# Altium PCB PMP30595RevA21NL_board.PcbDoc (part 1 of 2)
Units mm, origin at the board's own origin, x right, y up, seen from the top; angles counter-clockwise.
Board outline 110.49 x 76.2 mm, 2 copper layers (Top Layer, Bottom Layer), stack 1.575 mm thick; 77 components, 38 nets, 187 pads, 95 vias.
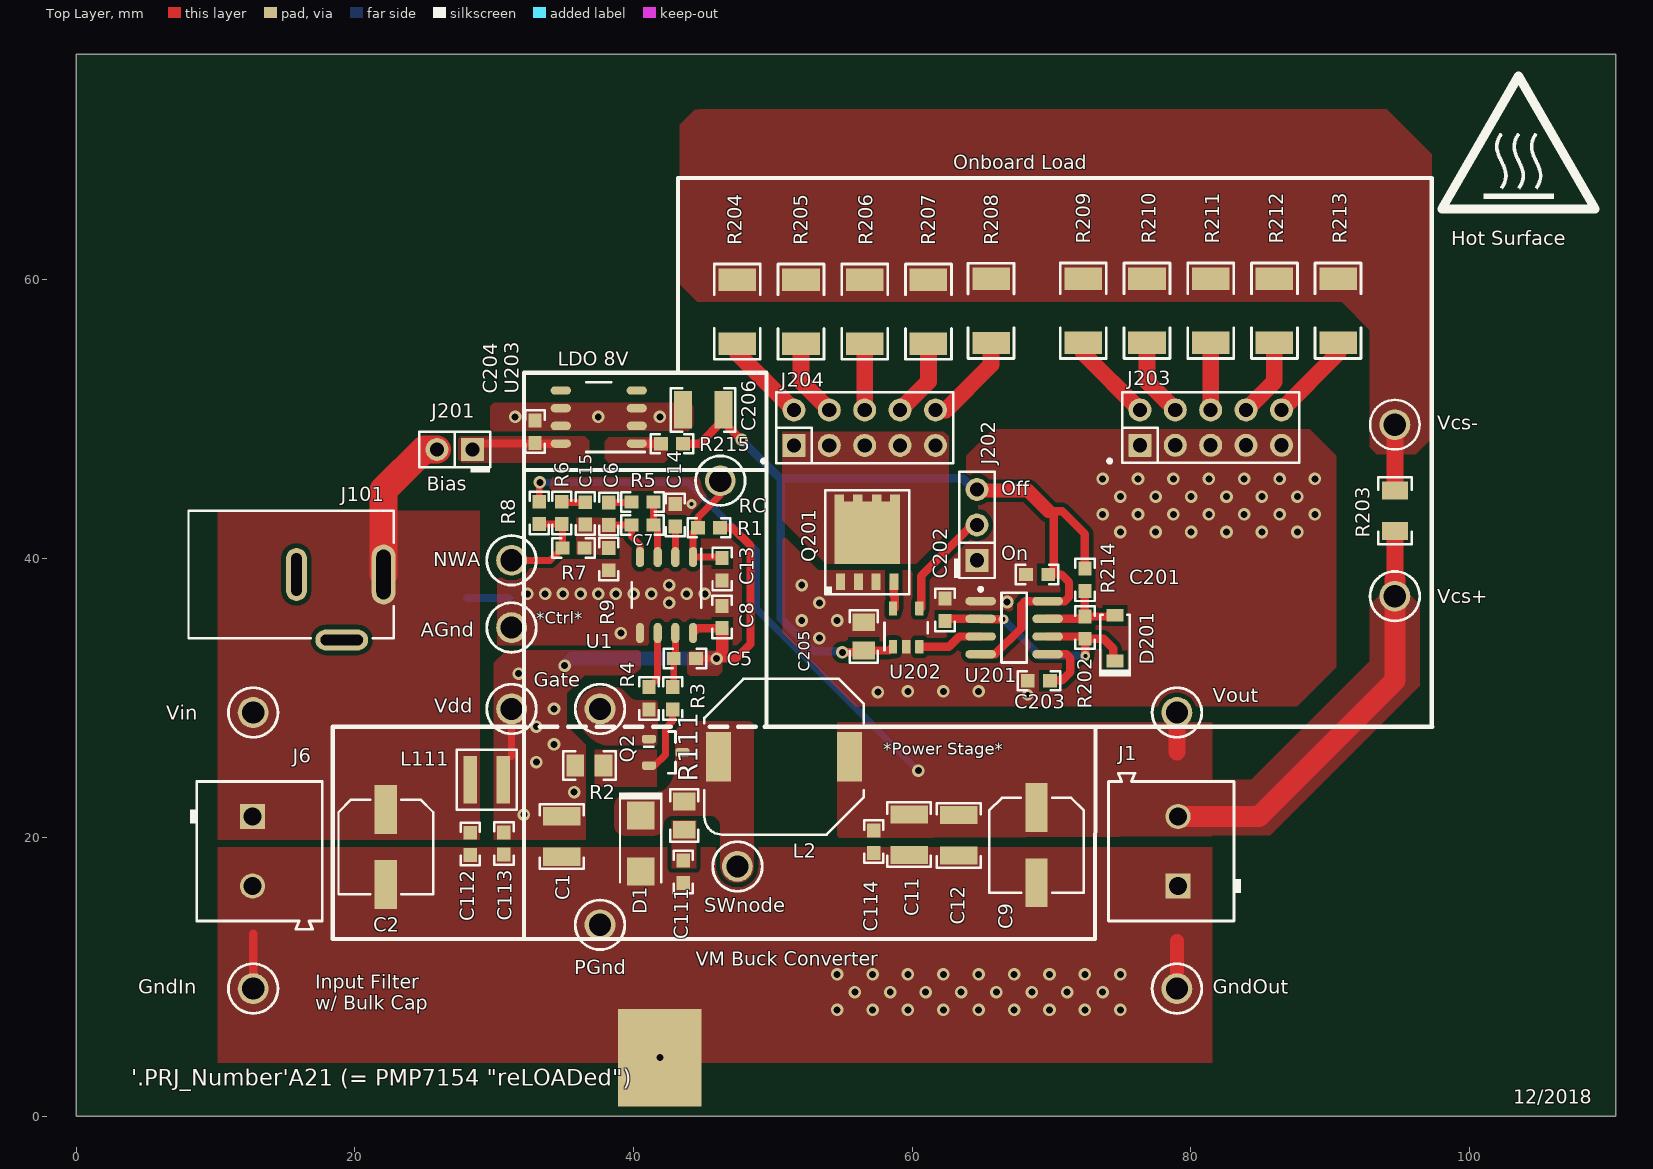
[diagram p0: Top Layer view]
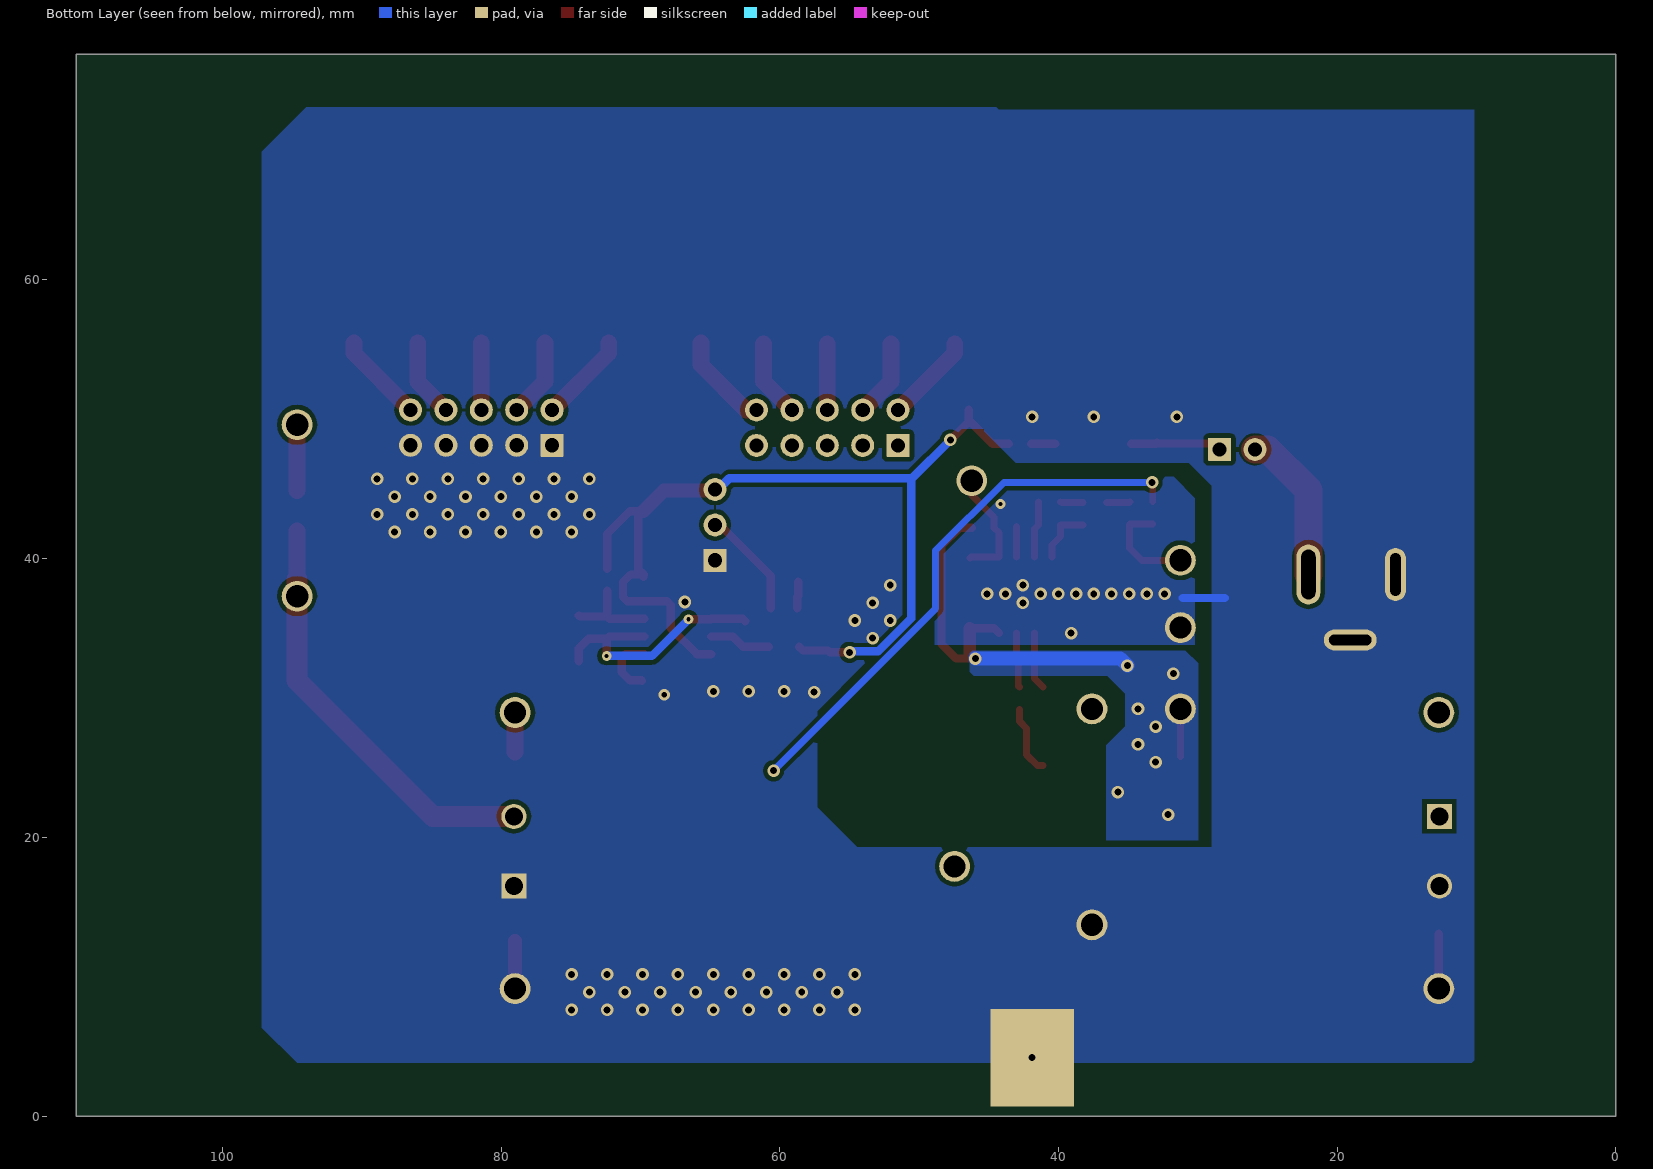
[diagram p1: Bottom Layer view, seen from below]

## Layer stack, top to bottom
Top Solder: solder mask 0.0102, Solder Resist, Dk 3.5
Top Layer: signal copper 0.0356
Dielectric1: core 1.5037, FR-4, Dk 4.8
Bottom Layer: signal copper 0.0356
Bottom Solder: solder mask 0.0102, Solder Resist, Dk 3.5

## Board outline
0,0 0,76.2 110.49,76.2 110.49,0

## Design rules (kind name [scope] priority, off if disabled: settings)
AcuteAngle [All] p1: minimum=4.50000000000000E+0001 checktracksonly=FALSE
AssemblyTestPointUsage [All] p1: valid=2
BoardOutlineClearance BoardOutlineClearance_MountingHoles [OnCopper and InComponentClass('Mounting Holes')] p1: gap=1 ignorepadtopadclearanceinfootprint=FALSE
BoardOutlineClearance BoardOutlineClearance_Poly [OnCopper and IsPoly] p2: gap=0.635 ignorepadtopadclearanceinfootprint=FALSE
BoardOutlineClearance [OnCopper and Not InComponentClass('Logo') and not InComponentClass('FiducialMark') and not InRegion(1000,500,4000,800) and not InPoly] p3: gap=1.905 ignorepadtopadclearanceinfootprint=FALSE
Clearance Clearance_Keepouts [((IsTrack Or IsArc) And Not InPoly) And IsFree and IsKeepOut vs ((IsTrack Or IsArc) And Not InPoly) And IsFree and IsKeepOut] p1: gap=0 ignorepadtopadclearanceinfootprint=FALSE
Clearance Clearance_Poly [InPolygon] p2: gap=0.32 ignorepadtopadclearanceinfootprint=TRUE
Clearance Clearance_FiducialMark [IsKeepOut and InComponentClass('FiducialMark') vs IsPad and InComponentClass('FiducialMark')] p3: gap=0 ignorepadtopadclearanceinfootprint=FALSE
Clearance [All] p4: gap=0.2 ignorepadtopadclearanceinfootprint=TRUE
ComponentClearance ComponentClearance_MountingHoles_FiducialMarks [InComponentClass('Mounting Holes') vs InComponentClass('FiducialMark')] p1: gap=1.27 collisioncheckmode=3 verticalgap=0.254 showdistances=FALSE
ComponentClearance ComponentClearance_Shunt [InComponentClass('Header') vs InComponentClass('Shunt')] p2: gap=0 collisioncheckmode=3 verticalgap=0 showdistances=FALSE
ComponentClearance ComponentClearance_Logo [InComponentClass('Logo')] p3: gap=1.27 collisioncheckmode=3 verticalgap=0.254 showdistances=FALSE
ComponentClearance ComponentClearance_ScrewToNut [(HasFootprint('NY PMS 440 0025 PH')) vs (HasFootprint('Keystone_1902C'))] p4: gap=0.127 collisioncheckmode=3 verticalgap=0.254 showdistances=FALSE
ComponentClearance ComponentClearance_MountingHoles [InComponentClass('Mounting Holes')] p5: gap=6.35 collisioncheckmode=3 verticalgap=2540 showdistances=FALSE
ComponentClearance ComponentClearance_SmallPassives [HasFootprint('0201*') or HasFootprint('0402*') or HasFootprint('0508') or HasFootprint('0603*') or HasFootprint('0612') or HasFootprint('0805*') or HasFootprint('0815*') or HasFootprint('0830*') or HasFootprint('1206*') or HasFootprint('1210*') or HasFootprint('1808*') or HasFootprint('1812*') or HasFootprint('1825*') or HasFootprint('2010*') or HasFootprint('2220*') or HasFootprint('2225*') or HasFootprint('2512*') or HasFootprint('2728*') or HasFootprint('3518*') vs HasFootprint('0201*') or HasFootprint('0402*') or HasFootprint('0508') or HasFootprint('0603*') or HasFootprint('0612') or HasFootprint('0805*') or HasFootprint('0815*') or HasFootprint('0830*') or HasFootprint('1206*') or HasFootprint('1210*') or HasFootprint('1808*') or HasFootprint('1812*') or HasFootprint('1825*') or HasFootprint('2010*') or HasFootprint('2220*') or HasFootprint('2225*') or HasFootprint('2512*') or HasFootprint('2728*') or HasFootprint('3518*')] p6: gap=0.38 collisioncheckmode=3 verticalgap=0.254 showdistances=FALSE
ComponentClearance ComponentClearance_THtoSMT [IsThruComponent vs IsSMTComponent] p7: gap=1.016 collisioncheckmode=3 verticalgap=0.762 showdistances=FALSE
ComponentClearance ComponentClearance_THtoTH [IsThruComponent vs IsThruComponent] p8: gap=0.762 collisioncheckmode=3 verticalgap=0.762 showdistances=FALSE
ComponentClearance [All] p9: gap=0.762 collisioncheckmode=3 verticalgap=0.254 showdistances=FALSE
DiffPairsRouting [All] p1: maxlimit=2.54 minlimit=0.254 mostfreqgap=0.254 toplayer_minwidth=0.381 toplayer_maxwidth=0.381 toplayer_prefwidth=0.381 bottomlayer_minwidth=0.381 bottomlayer_maxwidth=0.381 bottomlayer_prefwidth=0.381 maxuncoupledlength=25.4
FabricationTestPointUsage TestPointUsage [All] p1: valid=2 allowmultiple=FALSE
FabricationTestpoint Testpoint [All] p1: side=3 testpointundercomponent=TRUE minsize=1.016 maxsize=2.54 preferedsize=1.524 minholesize=0 maxholesize=1.016 preferedholesize=0.813 testpointgrid=0.025 allowsidetop=TRUE allowsidebottom=TRUE usegrid=TRUE gridtolerance=0
FanoutControl Fanout_LCC [IsLCC] p1: bgadir=Out bgaviamode=Centered fanoutstyle=Auto fanoutdirection=Alternating viagrid=0.025 // Fanout_LCC (Default Rule)
FanoutControl Fanout_BGA [IsBGA] p2: bgadir=Out bgaviamode=Centered fanoutstyle=Auto fanoutdirection=Alternating viagrid=0.025 // Fanout_BGA (Default Rule)
FanoutControl Fanout_Default [All] p4: bgadir=Out bgaviamode=Centered fanoutstyle=Auto fanoutdirection=Alternating viagrid=0.025 // Fanout_Default (Default Rule)
FanoutControl Fanout_Small [(CompPinCount < 5)] p5: bgadir=Out bgaviamode=Centered fanoutstyle=Auto fanoutdirection=OutThenIn viagrid=0.025 // Fanout_Small (Default Rule)
HoleSize [All] p1: absolutevalues=TRUE maxlimit=6.375 minlimit=0.3 maxpercent=80.000 minpercent=20.000
MinimumAnnularRing MinimumAnnularRing_ThermalPadVias [IsVia and InAnyComponent] p1: minimumring=0.15
MinimumAnnularRing [All] p2: minimumring=0.2
MinimumSolderMaskSliver MinimumSolderMaskSliver_Logo [InComponentClass('Logo') vs InComponentClass('Logo')] p1: minsoldermaskwidth=0.018
MinimumSolderMaskSliver [All] p2: minsoldermaskwidth=0.1
PlaneConnect [All] p1: planeconnectstyle=Relief reliefexpansion=0.254 reliefentries=4 reliefconductorwidth=0.254 reliefairgap=0.254
PolygonConnect [All] p1: connectstyle=Direct reliefconductorwidth=0.254 reliefentries=4 polygonreliefangle="90 Angle" airgapwidth=0.254
RoutingVias ThermalPadVias [IsVia and InAnyComponent] p1: holewidth=0.2 width=0.5 viastyle="Through Hole" minholewidth=0.2 minwidth=0.5 maxholewidth=0.33 maxwidth=0.6
RoutingVias [All] p2: holewidth=0.406 width=0.864 viastyle="Through Hole" minholewidth=0.2 minwidth=0.66 maxholewidth=1.016 maxwidth=1.651
SilkToBoardRegionClearance [Not ((IsComment or IsDesignator) And (Hide <> 'False')) and not InRegion(1000,500,4000,800)] p1:
SilkToSilkClearance SilkToSilkClearance_Pb-FreeLogo [(HasFootprint('Pb-Free_Overlay_Medium') OR HasFootprint('Pb-Free_Overlay_Small')) vs (HasFootprint('Pb-Free_Overlay_Medium') OR HasFootprint('Pb-Free_Overlay_Small'))] p1: silktosilkclearance=0
SilkToSilkClearance [All] p2: silktosilkclearance=0.1
SilkToSolderMaskClearance SilkToComponentPadClearance [(IsPad or IsFill or IsRegion) and InAnycomponent] p1: minsilkscreentomaskgap=0.127 clearancetoexposedcopper=TRUE
SilkToSolderMaskClearance "Silk to Solder Mask Opening" [All] p2: minsilkscreentomaskgap=0.1 clearancetoexposedcopper=FALSE
SolderMaskExpansion [All] p1: expansion=0.05
UnRoutedNet [All] p1: checkbadconnections=TRUE
Width [All] p1: maxlimit=2.54 minlimit=0.152 preferedwidth=0.254 checkconnectedcopper=TRUE
14 further rules are at their usual default settings.

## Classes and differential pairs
component class PMP30595RevA2_LOAD: C201 C202 C203 C204 C205 C206 D201 "Hot Surface" J201 J202 J203 J204 Q201 R202 R203 R204 R205 R206 R207 R208 R209 R210 R211 R212 R213 R214 R215 U201 U202 U203 Vcs+ Vcs-
component class PMP30595RevA2_BUCK: AGnd C1 C2 C5 C6 C7 C8 C9 C11 C12 C13 C14 C15 C111 C112 C113 C114 D1 Gate GndIn GndOut J1 J6 J101 L2 L111 NWA PGnd Q2 R1 R2 R3 R4 R5 R6 R7 R8 R9 R111 RC SWnode U1 Vdd Vin Vout
component class Header: J201 J202 J203 J204

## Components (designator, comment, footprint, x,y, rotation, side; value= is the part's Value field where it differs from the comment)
AGnd "5011" Keystone5011 31.242,35.052 r270 top
C1 "GRM32ER71E226KE15L" 1210_270 34.85,20.058 r270 top value=22uF
C2 "EEHZC1V680XP" SM_RADIAL_6.3BMM 22.225,19.304 r270 top value=68uF
C5 "GRM1885C1H101JA01D" 0603 43.684,32.827 r180 top value=100pF
C6 "GRM188R71E153KA01D" 0603 38.227,43.218 r90 top value=0.015uF
C7 "GRM1885C1H181JA01D" 0603 40.64,42.418 r0 top value=180pF
C8 "GCM188R71H104KA57D" 0603 46.355,35.814 r90 top value=0.1uF
C9 "EEHZC1E101XP" SM_RADIAL_6.3BMM 68.919,19.431 r270 top value=100uF
C11 "GRM32ER71A476KE15L" 1210_270 59.775,20.193 r270 top value=47uF
C12 "GRM32ER71A476KE15L" 1210_270 63.331,20.143 r270 top value=47uF
C13 "GRM188R71H471KA01D" 0603 46.355,39.243 r270 top value=470pF
C14 "GRM188R71E104KA01D" 0603 42.998,43.116 r90 top value=0.1uF
C15 "GRM188R71E562KA01D" 0603 36.534,43.243 r270 top value=5600pF
C111 "GRM188R71H471KA01D" 0603 43.561,17.526 r270 top value=470pF
C112 "GCM188R71H104KA57D" 0603 28.279,19.526 r270 top value=0.1uF
C113 "GCM188R71H104KA57D" 0603 30.692,19.558 r270 top value=0.1uF
C114 "GRM188R71E104KA01D" 0603 57.235,19.685 r270 top value=0.1uF
C201 "GRM188R71E104KA01D" 0603 68.961,38.862 r180 top value=0.1uF
C202 "GRM188R71E103KA01D" 0603 62.357,36.322 r90 top value=0.01uF
C203 "GRM188R71E104KA01D" 0603 69.088,31.234 r180 top value=0.1uF
C204 "GRM188R71E105KA12D" 0603 32.931,49.11 r90 top value=1uF
C205 "GRM21BR71E475KA73L" 0805_HV 56.515,34.417 r90 top value=4.7uF
C206 "GRM32ER71E226KE15L" 1210_270 44.997,50.673 r180 top value=22uF
D1 "B330A-13-F" SMA 40.513,19.558 r270 top value=30V
D201 "1N4148WFL-G3-08" SOD-123FL 74.549,34.29 r90 top value=100V
Gate "5012" Keystone5012 37.592,29.21 r270 top
GndIn "5011" Keystone5011 12.7,9.144 r0 top
GndOut "5011" Keystone5011 78.994,9.144 r90 top
"Hot Surface" "CAUTION HOT SURFACE" IEC_HotSurface_Medium 103.505,69.85 r0 top
J1 "691 101 710 002" Wurth_691101710002 79.079,19.002 r90 top
J6 "691 101 710 002" Wurth_691101710002 12.659,19.002 r270 top
J101 "RAPC722X" CONN_RAPC722X 8.315,38.862 r180 top
J201 "TSW-102-07-G-S" TSW-102-07-G-S 27.164,47.835 r180 top
J202 "TSW-103-07-G-S" TSW-103-07-G-S 64.643,42.418 r90 top
J203 "TSW-105-07-G-D" TSW-105-07-G-D 81.414,49.403 r0 top
J204 "TSW-105-07-G-D" TSW-105-07-G-D 56.586,49.397 r0 top
L2 "MSS1048-473MLB" MSS1048 50.8,25.781 r0 top value=47uH
L111 "XFL4020-102MEB" XFL4020 29.464,24.13 r0 top value=1uH
NWA "5014" Keystone5014 31.242,39.878 r270 top
PGnd "5011" Keystone5011 37.592,13.716 r0 top
Q2 "DMP3099L-7" SOT-23 42.306,26.096 r0 top value=-30V
Q201 "BSC093N04LS G" PG-TDSON-8 56.769,41.171 r90 top value=40V
R1 "CRCW060368K1FKEA" 0603 45.411,42.211 r0 top value=68.1k
R2 "CRM0805-FW-R050ELF" 0805_HV 36.83,25.146 r0 top value=0.05
R3 "CRCW06031K00FKEA" 0603 42.806,29.972 r270 top value=1.00k
R4 "CRCW06034R70JNEA" 0603 41.106,29.972 r270 top value=4.7
R5 "CRCW06034K02FKEA" 0603 40.64,44.069 r180 top value=4.02k
R6 "CRCW0603150RFKEA" 0603 34.85,43.28 r270 top value=150
R7 "CRCW060310K0FKEA" 0603 35.687,40.767 r0 top value=10.0k
R8 "CRCW060349R9FKEA" 0603 33.232,43.28 r270 top value=49.9
R9 "CRCW06031K62FKEA" 0603 38.227,39.967 r90 top value=1.62k
R111 "CRCW08057R50JNEA" 0805_HV 43.638,21.558 r90 top value=7.5
R202 "CRCW060371K5FKEA" 0603 72.39,35.048 r90 top value=71.5k
R203 "CSR1206FKR100" 1206 94.635,43.434 r90 top value=0.1
R204 "CRCW201049R9FKEF" 2010 47.442,57.723 r90 top value=49.9
R205 "CRCW201049R9FKEF" 2010 52.014,57.723 r90 top value=49.9
R206 "CRCW201049R9FKEF" 2010 56.586,57.723 r90 top value=49.9
R207 "CRCW201049R9FKEF" 2010 61.158,57.723 r90 top value=49.9
R208 "CRCW201049R9FKEF" 2010 65.656,57.779 r90 top value=49.9
R209 "CRCW201049R9FKEF" 2010 72.27,57.785 r90 top value=49.9
R210 "CRCW201049R9FKEF" 2010 76.842,57.785 r90 top value=49.9
R211 "CRCW201049R9FKEF" 2010 81.414,57.785 r90 top value=49.9
R212 "CRCW201049R9FKEF" 2010 85.986,57.785 r90 top value=49.9
R213 "CRCW201049R9FKEF" 2010 90.558,57.785 r90 top value=49.9
R214 "CRCW060371K5FKEA" 0603 72.39,38.481 r90 top value=71.5k
R215 "CRCW06031R00JNEA" 0603 42.756,48.235 r0 top value=1.0
RC "5012" Keystone5012 46.228,45.593 r270 top
SWnode "5012" Keystone5012 47.456,17.907 r90 top
U1 "TPS40200D" D0008A_N 42.363,37.385 r270 top
U201 "LMC555CM/NOPB" M08A_N 67.31,35.044 r0 top
U202 "UCC27517ADBVR" DBV0005A_N 59.563,35.052 r90 top
U203 "TL750L08CD" D0008A_N 37.503,50.159 r180 top
Vcs+ "5010" Keystone5010 94.635,37.302 r270 top
Vcs- "5126" Keystone5126 94.635,49.61 r270 top
Vdd "5010" Keystone5010 31.242,29.21 r270 top
Vin "5010" Keystone5010 12.7,28.956 r0 top
Vout "5010" Keystone5010 78.994,28.956 r0 top

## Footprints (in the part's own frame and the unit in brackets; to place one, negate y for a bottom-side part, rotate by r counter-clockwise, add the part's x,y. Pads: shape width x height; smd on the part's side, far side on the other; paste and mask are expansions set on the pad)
0603 [mm] "0603 from SM-752 data"
  rect 1x0.95 smd: 1(-0.8,0) 2(0.8,0)
  silkscreen extent -1.52,-0.69 1.52,0.69, body extent -0.87,-0.47 0.87,0.47, height 1
0805_HV [mil] "0805 with 30mil clearance between pads"
  rect 50x63 smd: 1(-40,0) 2(40,0)
  silkscreen extent -74,-40 74,40, body extent -43,-29 43,29, height 57
1206 [mm] "1206 from SM-752 data"
  rect 1.3x1.85 smd: 1(-1.45,0) 2(1.45,0)
  silkscreen extent -2.4,-1.21 2.4,1.21, body extent -1.7,-0.9 1.7,0.9, height 1.35
1210_270 [mm] "1210"
  rect 1.3x2.7 smd: 1(-1.45,0) 2(1.45,0)
  silkscreen extent -2.32,-1.57 2.32,1.57, body extent -1.7,-1.35 1.7,1.35, height 2.7
2010 [mm] "Chip Capacitor, Body 5.08x2.54mm, IPC Medium Density"
  rect 1.6x2.7 smd: 1(-2.3,0) 2(2.3,0)
  silkscreen extent -3.42,-1.65 3.42,1.65, body extent -2.73,-1.45 2.73,1.45, height 1.66
CONN_RAPC722X [mm] "Conn_DC Jack"
  oval 1.7x4.3 hole 1.01 slot 3.56 at 90 deg: 1(-13.741,0)
  oval 1.5x3.8 hole 0.76 slot 3.05 at 90 deg: 2(-7.493,0)
  oval 3.8x1.5 hole 0.76 slot 3.05 at 0 deg: 3(-10.744,4.7)
  silkscreen extent -14.48,-4.57 0.25,4.57, body extent -14.5,-4.57 0.23,4.83, height 11.18
D0008A_N [mm] "SOIC, 8-Leads, Body 4.9x3.9mm, Pitch 1.27mm, IPC Medium Density"
  oval 1.45x0.6 smd: 1(-2.725,1.905) 2(-2.725,0.635) 3(-2.725,-0.635) 4(-2.725,-1.905) 5(2.725,-1.905) 6(2.725,-0.635) 7(2.725,0.635) 8(2.725,1.905)
  silkscreen extent -3.3,-2.5 0.9,2.5, body extent -3,-2.45 3,2.45, height 1.63
DBV0005A_N [mm] "SOT23, 5-Leads, Body 2.9x1.6mm, Pitch 0.95mm, Lead Span 2.8mm, IPC Medium Density"
  rrect17% 1x0.6 smd: 1(-1.375,0.95) 2(-1.375,0) 3(-1.375,-0.95) 4(1.375,-0.95) 5(1.375,0.95)
  silkscreen extent -1.63,-1.55 0.38,1.55, body extent -1.42,-1.46 1.42,1.46, height 1.09
IEC_HotSurface_Medium [mm]
  silkscreen extent -5.51,-4.76 5.51,4.78
Keystone5010 [mil] "Keystone Multipurpose loops"
  round 87 hole 63: 1(0,0)
  silkscreen extent -70,-70 70,70, body extent -63,-63 63,62, height 319
Keystone5011 [mil] "Keystone Multipurpose loops"
  round 87 hole 63: 1(0,0)
  silkscreen extent -70,-70 70,70, body extent -63,-63 63,62, height 319
Keystone5012 [mil] "Keystone Multipurpose loops"
  round 87 hole 63: 1(0,0)
  silkscreen extent -70,-70 70,70, body extent -63,-63 63,62, height 319
Keystone5014 [mil] "Keystone Multipurpose loops"
  round 87 hole 63: 1(0,0)
  silkscreen extent -70,-70 70,70, body extent -63,-63 63,62, height 319
Keystone5126 [mil] "Keystone Multipurpose loops"
  round 87 hole 63: 1(0,0)
  silkscreen extent -70,-70 70,70, body extent -63,-63 63,62, height 319
M08A_N [mm] "SOIC, 8-Leads, Body 4.9x3.9mm, Pitch 1.27mm, IPC Medium Density"
  oval 2.2x0.6 smd: 1(-2.4,1.905) 2(-2.4,0.635) 3(-2.4,-0.635) 4(-2.4,-1.905) 5(2.4,-1.905) 6(2.4,-0.635) 7(2.4,0.635) 8(2.4,1.905)
  silkscreen extent -2.52,-2.5 0.9,2.88, body extent -2,-2.5 2,2.5, height 1.75
MSS1048 [mm] "Coilcraft recommended land pattern Document 462-2 Revised 06/09/09"
  rect 1.78x3.56 smd: 1(-4.7,0) 2(4.7,0)
  silkscreen extent -5.71,-5.59 5.71,5.59, body extent -5.15,-5.1 5.15,5.1, height 5.12
PG-TDSON-8 [mm] "Infineon recommended land pattern"
  rect 1.2x0.65 smd: 1(-2.825,1.905) 2(-2.825,0.635) 3(-2.825,-0.635) 4(-2.825,-1.905)
  rect 0.5x0.7 smd: 5(3.175,-2) 6(3.175,-0.675) 7(3.175,0.675) 8(3.175,2)
  rect 4.5x4.7 smd paste-2.25: 9(0.675,0)
  silkscreen extent -3.74,-3 3.74,3, body extent -3.17,-2.89 3.17,2.9, height 1.1
SM_RADIAL_6.3BMM [mm] "Nichicon 6.3x7.7"
  rect 3.5x1.6 smd: 1(-2.7,0) 2(2.7,0)
  silkscreen extent -3.4,-3.4 3.4,3.4, body extent -3.4,-3.4 3.4,3.4, height 8
SMA [mm] "Molded Diode, 2-Leads, Body 4.3x2.6mm, IPC Medium Density, based on OnSemi component dimensions and land pattern"
  rect 2x2 smd: 1(-2,0) 2(2,0)
  silkscreen extent -3.66,-1.57 2.79,1.57, body extent -2.6,-1.3 2.6,1.3, height 2.42
SOD-123FL [mm] "Copied from SOD-123"
  rect 0.915x1.22 smd: 1(-1.637,0) 2(1.637,0)
  silkscreen extent -2.74,-1.16 1.68,1.16, body extent -1.9,-0.9 1.9,0.9, height 1
SOT-23 [mm] "SOT23, 3-Leads, Body 2.9x1.3mm, Pitch 0.95mm, Lead Span 2.5mm, IPC Medium Density"
  rrect50% 1x0.6 smd: 1(-1.2,0.95) 2(-1.2,-0.95) 3(1.2,0)
  silkscreen extent -1.62,-1.5 0.7,1.5, body extent -1.16,-1.45 1.21,1.45, height 1
TSW-102-07-G-S [mm] "Samtec 100mil, 1x2, 230 mil above insulator"
  rrect6% 1.65x1.65 hole 1.016: 1(-1.27,0)
  round 1.65 hole 1.016: 2(1.27,0)
  silkscreen extent -2.54,-1.27 2.54,1.65, body extent -2.54,-1.27 2.54,1.27, height 8.38
TSW-103-07-G-S [mm] "Samtec 100mil, 1x3, 230 mil above insulator"
  rect 1.65x1.65 hole 1.016: 1(-2.54,0)
  round 1.65 hole 1.016: 2(0,0) 3(2.54,0)
  silkscreen extent -3.81,-1.27 3.81,1.65, body extent -3.81,-1.27 3.81,1.27, height 8.38
TSW-105-07-G-D [mm] "Samtec 100mil, 2x5, 230 mil above insulator"
  rrect6% 1.65x1.65 hole 1.016: 1(-5.08,-1.27)
  round 1.65 hole 1.016: 2(-5.08,1.27) 3(-2.54,-1.27) 4(-2.54,1.27) 5(0,-1.27) 6(0,1.27) 7(2.54,-1.27) 8(2.54,1.27) 9(5.08,-1.27) 10(5.08,1.27)
  silkscreen extent -7.37,-2.54 6.35,2.54, body extent -6.35,-2.54 6.35,2.54, height 8.38
Wurth_691101710002 [mm] "Terminal Block, 5 mm, 2x1, TH"
  rect 1.8x1.8 hole 1.3: 1(-2.5,0)
  round 1.8 hole 1.3: 2(2.5,0)
  silkscreen extent -5,-4.5 5.6,5, body extent -5.6,-4 5.6,5, height 12.5
XFL4020 [mm] "Coilcraft XFL4020 7/18/12"
  rect 0.98x3.4 smd: 1(-1.181,0) 2(1.181,0)
  silkscreen extent -2.16,-2.16 2.16,2.16, body extent -2.15,-2.15 2.15,2.15, height 2.1

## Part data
AGnd GndIn GndOut PGnd: "Test Point, Multipurpose, Black, TH", Color=Black, Manufacturer=Keystone, Supplier Part Number 1=36-5011-ND
C1 C206: "CAP, CERM, 22 µF, 25 V,+/- 10%, X7R, 1210", Cap_Case=1210, Manufacturer=MuRata, Supplier Part Number 1=490-5313-1-ND, TempCo=X7R, Tolerance_%=10, Value1="0.002334 ohm", Value2=25V, ValueDisplayed=22µF
C2: "CAP, Polymer Hybrid, 68 µF, 35 V,+/- 20%, 35 ohm, 6.3x7.7 SMD", Manufacturer=Panasonic, Supplier Part Number 1=P15474CT-ND, Tolerance_%=20, Value1="35 ohm", Value2=35V, ValueDisplayed=68µF
C5: "CAP, CERM, 100 pF, 50 V,+/- 5%, C0G/NP0, 0603", Cap_Case=0603, Manufacturer=MuRata, Supplier Part Number 1=490-1427-1-ND, TempCo=C0G/NP0, Tolerance_%=5, Value2=50V, ValueDisplayed=100pF
C6: "CAP, CERM, 0.015 µF, 25 V,+/- 10%, X7R, 0603", Cap_Case=0603, Manufacturer=MuRata, Supplier Part Number 1=81-GRM39X153K25D, TempCo=X7R, Tolerance_%=10, Value2=25V, ValueDisplayed=0.015µF
C7: "CAP, CERM, 180 pF, 50 V,+/- 5%, C0G/NP0, 0603", Cap_Case=0603, Manufacturer=MuRata, Supplier Part Number 1=490-1433-1-ND, TempCo=C0G/NP0, Tolerance_%=5, Value2=50V, ValueDisplayed=180pF
C8 C112 C113: "CAP, CERM, 0.1 µF, 50 V,+/- 10%, X7R, 0603", Cap_Case=0603, Manufacturer=MuRata, Supplier Part Number 1=490-4779-1-ND, TempCo=X7R, Tolerance_%=10, Value1="0.02 ohm", Value2=50V, ValueDisplayed=0.1µF
C9: "CAP, Polymer Hybrid, 100 µF, 25 V,+/- 20%, 30 ohm, 6.3x7.7 SMD", Manufacturer=Panasonic, Supplier Part Number 1=P15456CT-ND, Tolerance_%=20, Value1="30 ohm", Value2=25V, ValueDisplayed=100µF
C11 C12: "CAP, CERM, 47 µF, 10 V,+/- 10%, X7R, 1210", Cap_Case=1210, Manufacturer=MuRata, Supplier Part Number 1=490-5312-1-ND, TempCo=X7R, Tolerance_%=10, Value2=10V, ValueDisplayed=47µF
C13 C111: "CAP, CERM, 470 pF, 50 V,+/- 10%, X7R, 0603", Cap_Case=0603, Manufacturer=MuRata, Supplier Part Number 1=490-1489-1-ND, TempCo=X7R, Tolerance_%=10, Value2=50V, ValueDisplayed=470pF
C14 C114 C201 C203: "CAP, CERM, 0.1 µF, 25 V, +/- 10%, X7R, 0603", Cap_Case=0603, Manufacturer=MuRata, Supplier Part Number 1=490-1524-1-ND, TempCo=X7R, Tolerance_%=10, Value1=Unknown, Value2=25V, ValueDisplayed=0.1µF
C15: "CAP, CERM, 5600 pF, 25 V,+/- 10%, X7R, 0603", Cap_Case=0603, Manufacturer=MuRata, Supplier Part Number 1=GRM188R71E562KA01D-ND, TempCo=X7R, Tolerance_%=10, Value2=25V, ValueDisplayed=5600pF
C202: "CAP, CERM, 0.01 µF, 25 V,+/- 10%, X7R, 0603", Cap_Case=0603, Manufacturer=MuRata, Supplier Part Number 1=490-1520-1-ND, TempCo=X7R, Tolerance_%=10, Value2=25V, ValueDisplayed=0.01µF
C204: "CAP, CERM, 1 µF, 25 V,+/- 10%, X7R, 0603", Cap_Case=0603, Manufacturer=MuRata, Supplier Part Number 1=490-5307-1-ND, TempCo=X7R, Tolerance_%=10, Value2=25V, ValueDisplayed=1µF
C205: "CAP, CERM, 4.7 µF, 25 V,+/- 10%, X7R, 0805", Cap_Case=0805, Manufacturer=MuRata, Supplier Part Number 1=490-9962-1-ND, TempCo=X7R, Tolerance_%=10, Value2=25V, ValueDisplayed=4.7µF
D1: "Diode, Schottky, 30 V, 3 A, SMA", Manufacturer="Diodes Inc.", Supplier Part Number 1=B330A-FDICT-ND, Value1=3A, Value2=0.5V
D201: "Diode, Switching, 100 V, 0.15 A, SOD-123FL", Manufacturer=Vishay-Semiconductor, Supplier Part Number 1=1N4148WFL-G3-08GICT-ND, Value1=0.15A, Value2=1.2V
Gate RC SWnode: "Test Point, Multipurpose, White, TH", Color=White, Manufacturer=Keystone, Supplier Part Number 1=36-5012-ND
"Hot Surface": library part IEC_HotSurface, "IEC 61010-1 Hot Surface Warning"
J1 J6: "Terminal Block, 5 mm, 2x1, Tin, TH", Manufacturer="Wurth Elektronik", Supplier Part Number 1=732-2026-ND
J101: "Power Jack, mini, 2.1mm OD, R/A, TH", Manufacturer=Switchcraft, Supplier Part Number 1=SC1313-ND
J201: "Header, 100mil, 2x1, Gold, TH", Color=Black, Current_A=6.3, Manufacturer=Samtec, Supplier Part Number 1=SAM1029-02-ND, Voltage_V=550
J202: "Header, 100mil, 3x1, Gold, TH", Color=Black, Current_A=6.3, Manufacturer=Samtec, Supplier Part Number 1=SAM1029-03-ND, Voltage_V=550
J203 J204: "Header, 100mil, 5x2, Gold, TH", Color=Black, Current_A=6.3, Manufacturer=Samtec, Supplier Part Number 1=SAM1028-05-ND, Voltage_V=550
L2: "Inductor, Shielded Drum Core, Ferrite, 47 µH, 2.2 A, 0.13 ohm, SMD", Manufacturer=Coilcraft, Value1="0.13 ohm", Value2=2.2A, ValueDisplayed=47µH
L111: "Inductor, Shielded, Composite, 1 µH, 5.4 A, 0.01 ohm, SMD", Manufacturer=Coilcraft, Supplier Part Number 1=994-XFL4020-102MEB, Value1="0.01 ohm", Value2=5.4A, ValueDisplayed=1µH
NWA: "Test Point, Multipurpose, Yellow, TH", Color=Yellow, Manufacturer=Keystone, Supplier Part Number 1=36-5014-ND
Q2: "MOSFET, P-CH, -30 V, -3.8 A, AEC-Q101, SOT-23", Alternate Manufacturer=None, Manufacturer="Diodes Inc.", Supplier Part Number 1=DMP3099L-7DICT-ND, Value1="? ohm", Value2="5.2 nC"
Q201: "MOSFET, N-CH, 40 V, 49 A, PG-TDSON-8", Alternate Manufacturer=None, Manufacturer="Infineon Technologies", Supplier Part Number 1="BSC093N04LS GCT-ND", Value1="0.0137 ohm", Value2="18 nC"
R1: "RES, 68.1 k, 1%, 0.1 W, 0603", Manufacturer=Vishay-Dale, Power_W=0.1, Supplier Part Number 1=541-68.1KHCT-ND, TempCo="100 ppm/C", Tolerance_%=1, Value1=1%, Value2=0.1W, Value_Code=68k1, ValueDisplayed=68.1k
R2: "RES, 0.05, 1%, 0.25 W, 0805", Manufacturer=Bourns, Power_W=0.25, Supplier Part Number 1=1865234, TempCo="150 ppm/C", Tolerance_%=1, Value1=1%, Value2=0.25W, Value_Code=R050, ValueDisplayed=0.05
R3: "RES, 1.00 k, 1%, 0.1 W, 0603", Manufacturer=Vishay-Dale, Power_W=0.1, Supplier Part Number 1=541-1.00KHCT-ND, TempCo="100 ppm/C", Tolerance_%=1, Value1=1%, Value2=0.1W, Value_Code=1k00, ValueDisplayed=1.00k
R4: "RES, 4.7, 5%, 0.1 W, 0603", Manufacturer=Vishay-Dale, Power_W=0.1, Supplier Part Number 1=541-4.7GCT-ND, TempCo="200 ppm/C", Tolerance_%=5, Value1=5%, Value2=0.1W, Value_Code=4R70, ValueDisplayed=4.7
R5: "RES, 4.02 k, 1%, 0.1 W, 0603", Manufacturer=Vishay-Dale, Power_W=0.1, Supplier Part Number 1=541-4.02KHCT-ND, TempCo="100 ppm/C", Tolerance_%=1, Value1=1%, Value2=0.1W, Value_Code=4k02, ValueDisplayed=4.02k
R6: "RES, 150, 1%, 0.1 W, 0603", Manufacturer=Vishay-Dale, Power_W=0.1, Supplier Part Number 1=541-150HCT-ND, TempCo="100 ppm/C", Tolerance_%=1, Value1=1%, Value2=0.1W, Value_Code=150R, ValueDisplayed=150
R7: "RES, 10.0 k, 1%, 0.1 W, 0603", Manufacturer=Vishay-Dale, Power_W=0.1, Supplier Part Number 1=541-10.0KHCT-ND, TempCo="100 ppm/C", Tolerance_%=1, Value1=1%, Value2=0.1W, Value_Code=10k0, ValueDisplayed=10.0k
R8: "RES, 49.9, 1%, 0.1 W, 0603", Manufacturer=Vishay-Dale, Power_W=0.1, Supplier Part Number 1=541-49.9HCT-ND, TempCo="100 ppm/C", Tolerance_%=1, Value1=1%, Value2=0.1W, Value_Code=49R9, ValueDisplayed=49.9
R9: "RES, 1.62 k, 1%, 0.1 W, 0603", Manufacturer=Vishay-Dale, Power_W=0.1, Supplier Part Number 1=541-1.62KHCT-ND, TempCo="100 ppm/C", Tolerance_%=1, Value1=1%, Value2=0.1W, Value_Code=1k62, ValueDisplayed=1.62k
R111: "RES, 7.5, 5%, 0.125 W, 0805", Manufacturer=Vishay-Dale, Power_W=0.125, Supplier Part Number 1=541-7.5ACT-ND, TempCo="200 ppm/C", Tolerance_%=5, Value1=5%, Value2=0.125W, Value_Code=7R50, ValueDisplayed=7.5
R202 R214: "RES, 71.5 k, 1%, 0.1 W, 0603", Manufacturer=Vishay-Dale, Power_W=0.1, Supplier Part Number 1=541-71.5KHCT-ND, TempCo="100 ppm/C", Tolerance_%=1, Value1=1%, Value2=0.1W, Value_Code=71k5, ValueDisplayed=71.5k
R203: "RES, 0.1, 1%, 0.5 W, 1206", Manufacturer="Stackpole Electronics Inc", Power_W=0.5, Supplier Part Number 1=CSR1206FKR100CT-ND, TempCo="100 ppm/C", Tolerance_%=1, Value1=1%, Value2=0.5W, Value_Code=R100, ValueDisplayed=0.1
R204 R205 R206 R207 R208 R209 R210 R211 R212 R213: "RES, 49.9, 1%, 0.75 W, AEC-Q200 Grade 0, 2010", Manufacturer=Vishay-Dale, Power_W=0.75, Supplier Part Number 1=541-49.9ACCT-ND, TempCo="100 ppm/C", Tolerance_%=1, Value1=1%, Value2=0.75W, Value_Code=49R9, ValueDisplayed=49.9
R215: "RES, 1.0, 5%, 0.1 W, 0603", Manufacturer=Vishay-Dale, Power_W=0.1, Supplier Part Number 1=541-1.0GCT-ND, TempCo="200 ppm/C", Tolerance_%=5, Value1=5%, Value2=0.1W, Value_Code=1R00, ValueDisplayed=1.0
U1: "Wide Input Non-Synchronous Buck DC/DC Controller, D0008A (SOIC-8)", Alternate Manufacturer="Texas Instruments"
U201: "CMOS Timer, 8-pin Narrow SOIC, Pb-Free", Manufacturer="Texas Instruments", PackageTopMarking=NSZXTT*LMC*555CM, PowerWise=N, Supplier Part Number 1=LMC555CM-ND
U202: library part UCC27517DBVR, "4A/4A Single Channel High-speed Low-side Gate Driver, DBV0005A (SOT-23-5)", Alternate Manufacturer="Texas Instruments", Alternate PartNumber=UCC27517DBVT
U203: "Single Output LDO, 150 mA, Fixed 8 V Output, 9 to 26 V Input, with Low IQ, 8-pin SOIC (D), 0 to 125 degC, Green (RoHS & no Sb/Br)", Alternate Manufacturer="Texas Instruments", Alternate PartNumber=Equivalent, Rating=Catalog, Supplier Part Number 1=296-8004-5-ND
Vcs+ Vdd Vin Vout: "Test Point, Multipurpose, Red, TH", Color=Red, Manufacturer=Keystone, Supplier Part Number 1=36-5010-ND
Vcs-: "Test Point, Multipurpose, Green, TH", Color=Green, Manufacturer=Keystone, Supplier Part Number 1=36-5126-ND

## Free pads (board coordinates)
  rect 6x7 hole 0.5: 1(41.893,4.191)

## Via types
v1: diameter 0.9, hole 0.5, Top Layer to Bottom Layer, 81 vias
v2: diameter 0.9, hole 0.5, Top Layer to Bottom Layer, tented top, 10 vias
v3: diameter 0.7, hole 0.3, Top Layer to Bottom Layer, 2 vias
v4: diameter 0.7, hole 0.3, Top Layer to Bottom Layer, tented top, 1 vias
v5: diameter 0.8, hole 0.4, Top Layer to Bottom Layer, tented top, 1 vias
